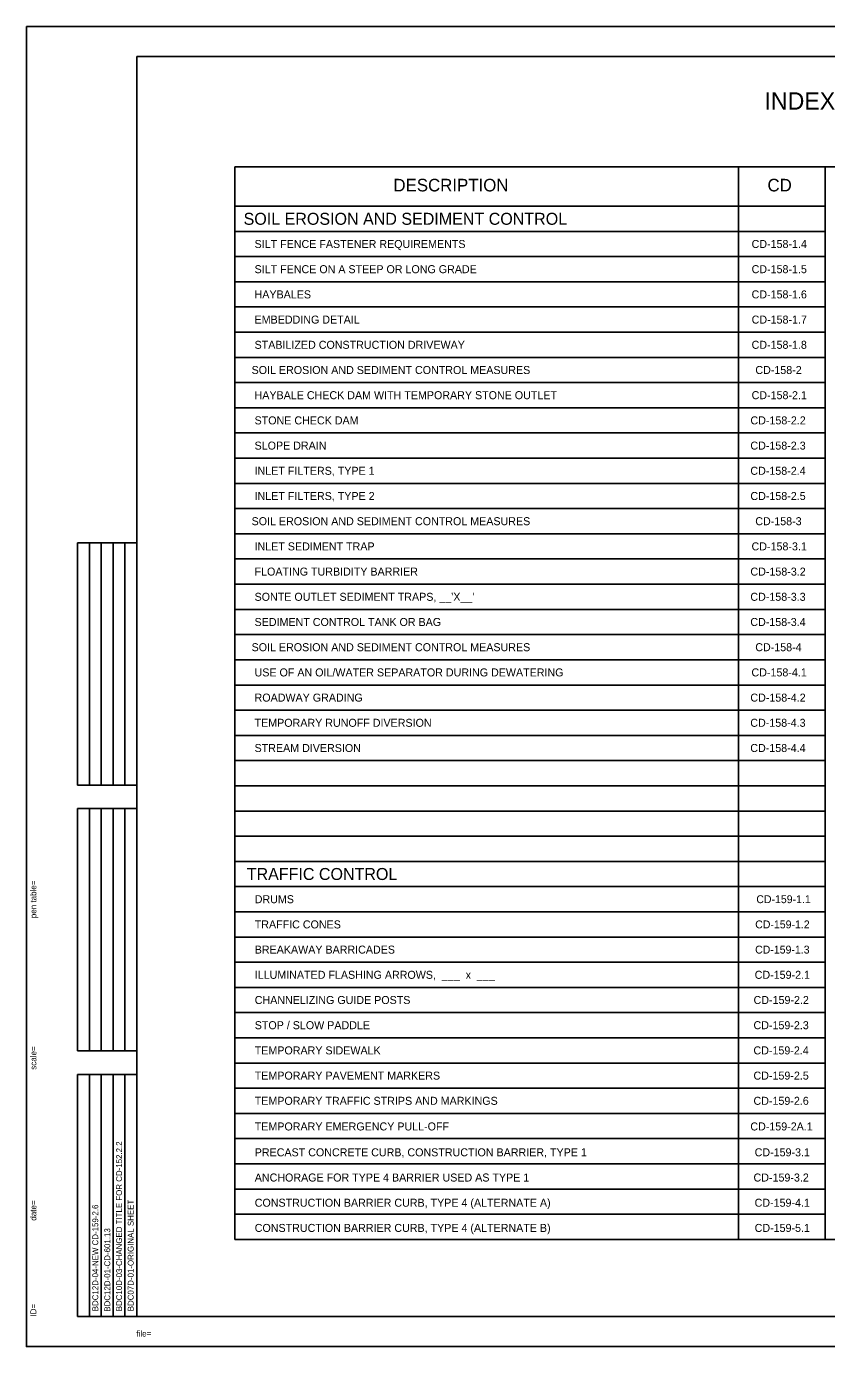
# Model space of a CAD drawing. Extents: x 503613 to 504661, y 499104 to 499764.
# Drawn here: x 503613 to 504013, y 499104 to 499764 of the extents above; entities that cross this region are included whole.
import ezdxf

# ---------------------------------------------------------------- set-up
doc = ezdxf.new("R2010")
doc.units = 0
for name, color, linetype in [('1', 7, 'Continuous'), ('39', 7, 'Continuous'), ('41', 7, 'Continuous')]:
    doc.layers.add(name, color=color, linetype=linetype)

msp = doc.modelspace()

# ---------------------------------------------------------------- linework, layer by layer
at = {"layer": '1'}
for p, q in [((504661.22, 499764.48), (503613.04, 499764.48)), ((504658.22, 499749.48), (503668.22, 499749.48)), ((503668.22, 499749.48), (503668.22, 499119.48)), ((503717.27, 499694.28), (504603.1, 499694.28)), ((503717.27, 499158.06), (503717.27, 499694.28)), ((503717.27, 499674.59), (503717.27, 499694.28)), ((503969.24, 499158.06), (503969.24, 499694.28)), ((503969.24, 499674.59), (503969.24, 499694.28)), ((504012.55, 499158.06), (504012.55, 499694.28)), ((504012.55, 499674.59), (504012.55, 499694.28)), ((503717.27, 499674.59), (504012.55, 499674.59)), ((503717.27, 499662), (504012.55, 499662)), ((503717.27, 499649.4), (504012.55, 499649.4)), ((503717.27, 499636.8), (504012.55, 499636.8)), ((503717.27, 499624.2), (504012.55, 499624.2)), ((503717.27, 499611.6), (504012.55, 499611.6)), ((503717.27, 499599), (504012.55, 499599)), ((503717.27, 499586.41), (504012.55, 499586.41)), ((503717.27, 499573.81), (504012.55, 499573.81)), ((503717.27, 499561.21), (504012.55, 499561.21)), ((503717.27, 499548.61), (504012.55, 499548.61)), ((503717.27, 499536.01), (504012.55, 499536.01)), ((503717.27, 499523.41), (504012.55, 499523.41)), ((503717.27, 499510.82), (504012.55, 499510.82)), ((503638.69, 499506.29), (503668.22, 499506.29)), ((503638.69, 499385.22), (503638.69, 499506.29)), ((503644.59, 499385.22), (503644.59, 499506.29)), ((503650.5, 499385.22), (503650.5, 499506.29)), ((503656.41, 499385.22), (503656.41, 499506.29)), ((503662.31, 499385.22), (503662.31, 499506.29)), ((503717.27, 499498.22), (504012.55, 499498.22)), ((503717.27, 499485.62), (504012.55, 499485.62)), ((503717.27, 499473.02), (504012.55, 499473.02)), ((503717.27, 499460.42), (504012.55, 499460.42)), ((503717.27, 499447.82), (504012.55, 499447.82)), ((503717.27, 499435.22), (504012.55, 499435.22)), ((503717.27, 499422.63), (504012.55, 499422.63)), ((503717.27, 499410.03), (504012.55, 499410.03)), ((503717.27, 499397.43), (504012.55, 499397.43)), ((503668.22, 499385.22), (503638.69, 499385.22)), ((503717.27, 499384.83), (504012.55, 499384.83)), ((503638.69, 499373.41), (503668.22, 499373.41)), ((503638.69, 499252.35), (503638.69, 499373.41)), ((503644.59, 499252.35), (503644.59, 499373.41)), ((503650.5, 499252.35), (503650.5, 499373.41)), ((503656.41, 499252.35), (503656.41, 499373.41)), ((503662.31, 499252.35), (503662.31, 499373.41)), ((503717.27, 499372.23), (504012.55, 499372.23)), ((503717.27, 499359.63), (504012.55, 499359.63)), ((503717.27, 499347.04), (504012.55, 499347.04)), ((503717.27, 499334.44), (504012.55, 499334.44)), ((503717.27, 499321.84), (504012.55, 499321.84)), ((503717.27, 499309.24), (504012.55, 499309.24)), ((503717.27, 499296.64), (504012.55, 499296.64)), ((503717.27, 499284.04), (504012.55, 499284.04)), ((503717.27, 499271.44), (504012.55, 499271.44)), ((503717.27, 499258.85), (504012.55, 499258.85)), ((503668.22, 499252.35), (503638.69, 499252.35)), ((503717.27, 499246.25), (504012.55, 499246.25)), ((503638.69, 499119.48), (503638.69, 499240.54)), ((503638.69, 499240.54), (503668.22, 499240.54)), ((503644.59, 499119.48), (503644.59, 499240.54)), ((503650.5, 499119.48), (503650.5, 499240.54)), ((503656.41, 499119.48), (503656.41, 499240.54)), ((503662.31, 499119.48), (503662.31, 499240.54)), ((503717.27, 499233.65), (504012.55, 499233.65)), ((503717.27, 499221.05), (504012.55, 499221.05)), ((503717.27, 499208.45), (504012.55, 499208.45)), ((503717.27, 499195.85), (504012.55, 499195.85)), ((503717.27, 499183.26), (504012.55, 499183.26)), ((503717.27, 499170.66), (504012.55, 499170.66)), ((503717.27, 499158.06), (504603.1, 499158.06)), ((503717.27, 499158.06), (504012.55, 499158.06)), ((503668.22, 499119.48), (503638.69, 499119.48)), ((503668.22, 499119.48), (504658.22, 499119.48)), ((504661.22, 499104.48), (503613.04, 499104.48))]:
    msp.add_line(p, q, dxfattribs=at)
at = {"layer": '41'}
msp.add_lwpolyline([(503613.04, 499764.48), (504661.22, 499764.48), (504661.22, 499104.48), (503613.04, 499104.48)], close=True, dxfattribs=at)

# ---------------------------------------------------------------- texts
at = {"layer": '1'}
for s, height, p in [('DESCRIPTION', 6.2992, (503796.64, 499681.98)), ('CD', 6.299, (503983.75, 499681.98))]:
    msp.add_text(s, height=height, dxfattribs=at).set_placement(p)
for s, height, rotation, p in [('...................pentable..................', 0.0432, 90, (503618.04, 499342.54)), ('pen table=', 3, 90, (503618.04, 499318.64)), ('......scale......', 0.0432, 90, (503618.04, 499257.54)), ('scale=', 3, 90, (503618.04, 499242.87)), ('.......time......', 0.0432, 90, (503618.04, 499180.54)), ('date=', 3, 90, (503618.04, 499167.41)), ('ID=', 3, 90, (503618.04, 499119.5)), ('............who............', 0.0432, 90, (503618.04, 499127.48)), ('file=', 3, 360, (503668.05, 499109.48)), ('...................bob..................', 0.0432, 360, (503678.04, 499109.48))]:
    msp.add_text(s, height=height, rotation=rotation, dxfattribs=at).set_placement(p)
at = {"layer": '39'}
for s, height, p in [('INDEX FOR STANDARD ROADWAY CONSTRUCTION DETAILS', 8.6614, (503982.24, 499722.87)), ('SOIL EROSION AND SEDIMENT CONTROL ', 6, (503721.7, 499665.29)), (' SILT FENCE FASTENER REQUIREMENTS', 4, (503725.7, 499653.7)), ('CD-158-1.4', 4, (503975.81, 499653.7)), (' SILT FENCE ON A STEEP OR LONG GRADE', 4, (503725.7, 499641.1)), ('CD-158-1.5', 4, (503975.81, 499641.1)), (' HAYBALES', 4, (503725.7, 499628.5)), ('CD-158-1.6', 4, (503975.81, 499628.5)), (' EMBEDDING DETAIL', 4, (503725.7, 499615.9)), ('CD-158-1.7', 4, (503975.83, 499615.9)), (' STABILIZED CONSTRUCTION DRIVEWAY', 4, (503725.7, 499603.3)), ('CD-158-1.8', 4, (503975.81, 499603.3)), ('SOIL EROSION AND SEDIMENT CONTROL MEASURES', 4, (503725.7, 499590.7)), ('CD-158-2', 4, (503977.69, 499590.7)), (' HAYBALE CHECK DAM WITH TEMPORARY STONE OUTLET', 4, (503725.7, 499578.11)), ('CD-158-2.1', 4, (503975.81, 499578.11)), (' STONE CHECK DAM', 4, (503725.7, 499565.51)), ('CD-158-2.2', 4, (503975.24, 499565.51)), (' SLOPE DRAIN', 4, (503725.7, 499552.91)), ('CD-158-2.3', 4, (503975.21, 499552.91)), (' INLET FILTERS, TYPE 1', 4, (503725.7, 499540.31)), ('CD-158-2.4', 4, (503975.2, 499540.31)), (' INLET FILTERS, TYPE 2', 4, (503725.7, 499527.71)), ('CD-158-2.5', 4, (503975.21, 499527.71)), ('SOIL EROSION AND SEDIMENT CONTROL MEASURES', 4, (503725.7, 499515.11)), ('CD-158-3', 4, (503977.65, 499515.11)), (' INLET SEDIMENT TRAP', 4, (503725.7, 499502.52)), ('CD-158-3.1', 4, (503975.79, 499502.52)), (' FLOATING TURBIDITY BARRIER', 4, (503725.7, 499489.92)), ('CD-158-3.2', 4, (503975.22, 499489.92)), (" SONTE OUTLET SEDIMENT TRAPS, __'X__'", 4, (503725.7, 499477.32)), ('CD-158-3.3', 4, (503975.19, 499477.32)), (' SEDIMENT CONTROL TANK OR BAG', 4, (503725.7, 499464.72)), ('CD-158-3.4', 4, (503975.18, 499464.72)), ('SOIL EROSION AND SEDIMENT CONTROL MEASURES', 4, (503725.7, 499452.12)), ('CD-158-4', 4, (503977.65, 499452.12)), (' USE OF AN OIL/WATER SEPARATOR DURING DEWATERING', 4, (503725.7, 499439.52)), ('CD-158-4.1', 4, (503975.76, 499439.52)), (' ROADWAY GRADING', 4, (503725.7, 499426.92)), ('CD-158-4.2', 4, (503975.2, 499426.92)), (' TEMPORARY RUNOFF DIVERSION', 4, (503725.7, 499414.33)), ('CD-158-4.3', 4, (503975.16, 499414.33)), (' STREAM DIVERSION', 4, (503725.7, 499401.73)), ('CD-158-4.4', 4, (503975.16, 499401.73)), ('TRAFFIC CONTROL', 6, (503723.27, 499337.74)), ('DRUMS', 4, (503727.27, 499326.14)), ('CD-159-1.1', 3.937, (503978.17, 499326.17)), ('TRAFFIC CONES', 4, (503727.27, 499313.54)), ('CD-159-1.2', 3.937, (503977.62, 499313.57)), ('BREAKAWAY BARRICADES', 4, (503727.27, 499300.94)), ('CD-159-1.3', 3.937, (503977.58, 499300.97)), ('ILLUMINATED FLASHING ARROWS,  ___  x  ___ ', 4, (503727.27, 499288.34)), ('CD-159-2.1', 4, (503977.36, 499288.34)), ('CHANNELIZING GUIDE POSTS', 4, (503727.27, 499275.74)), ('CD-159-2.2', 4, (503976.8, 499275.74)), ('STOP / SLOW PADDLE', 4, (503727.27, 499263.15)), ('CD-159-2.3', 4, (503976.76, 499263.15)), ('TEMPORARY SIDEWALK', 4, (503727.27, 499250.55)), ('CD-159-2.4', 4, (503976.75, 499250.55)), ('TEMPORARY PAVEMENT MARKERS', 4, (503727.27, 499237.95)), ('CD-159-2.5', 4, (503976.76, 499237.95)), ('TEMPORARY TRAFFIC STRIPS AND MARKINGS', 4, (503727.27, 499225.35)), ('CD-159-2.6', 4, (503976.76, 499225.35)), ('TEMPORARY EMERGENCY PULL-OFF', 4, (503727.27, 499212.54)), ('CD-159-2A.1', 4, (503975.18, 499212.54)), ('PRECAST CONCRETE CURB, CONSTRUCTION BARRIER, TYPE 1', 4, (503727.27, 499199.6)), ('CD-159-3.1', 4, (503977.34, 499199.6)), ('ANCHORAGE FOR TYPE 4 BARRIER USED AS TYPE 1', 4, (503727.27, 499187)), ('CD-159-3.2', 4, (503976.78, 499187)), ('CONSTRUCTION BARRIER CURB, TYPE 4 (ALTERNATE A)', 4, (503727.27, 499174.4)), ('CD-159-4.1', 4, (503977.32, 499174.4)), ('CONSTRUCTION BARRIER CURB, TYPE 4 (ALTERNATE B)', 4, (503727.27, 499161.8)), ('CD-159-5.1', 4, (503977.34, 499161.8))]:
    msp.add_text(s, height=height, dxfattribs=at).set_placement(p)
for s, p in [('BDC10D-03-CHANGED TITLE FOR CD-152.2.2', (503660.89, 499122.15)), ('BDC12D-04-NEW CD-159-2.6', (503648.97, 499122.15)), ('BDC07D-01-ORIGINAL SHEET', (503666.69, 499122.15)), ('BDC12D-01-CD-601.13', (503654.98, 499121.95))]:
    msp.add_text(s, height=2.9528, rotation=90, dxfattribs=at).set_placement(p)

doc.saveas('drawing.dxf')
